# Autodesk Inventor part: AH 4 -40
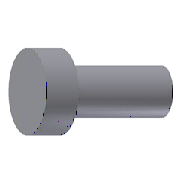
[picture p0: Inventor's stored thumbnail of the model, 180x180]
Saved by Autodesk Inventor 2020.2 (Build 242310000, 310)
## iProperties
Manager: www.cadconsulting.pl
Company: Fabian Stasiak CAD Consulting
Created: 2014-02
Part Number: AH 4 -40
Material: DIN 1.2210
Description: Ejector pins-hardened
Document SubType Name: Modeling
Standard: DIN 1530/ISO 6751
Designer: F.Stasiak
Standard Revision: 1
Manufacturer: DME
Language: pl-PL
Size Designation: 4 -40
Categories: <MemberInstance><Categories><Category DisplayName="Forma wtryskowa" InternalName="349578f2-f4d4-4954-8c09-8e99297a61c0" Mnemonic="MOLD"><Category DisplayName="K
Mass: 0.191827 g
Surface Area: 2.51725 cm^2
Volume: 0.191827 cm^3
Density: 7.85 g/cm^3
Appearance: Aluminium - ciemne
Catalog Web Link: www.expertbooks.pl
IsCustomPart: 1
Author: F.Stasiak
Subject: Zbiór ćwiczeń. Autodesk Inventor 2020. Kurs Professional
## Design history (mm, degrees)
sketch "Sketch1"
  geometry: L1 (0, 4)-(3, 4); L2 (0, 0)-(0, 4); L3 (3, 2)-(40, 2); L4 (40, 2)-(40, 0); L5 (0, 0)-(40, 0); L6 (3, 4)-(3, 2); 2 further points
  constraints: 12 end point, 4 point on line, 2 horizontal, 2 perpendicular, 1 coincident
  dimensions: "d6" = 3 distance of L1.start L1.end (derived); "d9" = 40 distance between parallel lines of L4 L2 (derived); "d10" = 8 diameter of L1 L5 (derived); "d13" = 4 diameter of L3 L5 (derived)
revolve "Revolution1" sketch "Sketch1" stored, may be unused: angle "d11" = 90 deg
fillet "Fillet1" dims "d29" = 0.3 (derived)
workplane "Work Plane1"
sketch "Sketch2"
  geometry: L1 (4, -1.5)-(-4, -1.5) reference; L2 (-4, -1.5)-(-4, 1.5) reference; 4 further points
  constraints: 2 midpoint, 1 horizontal alignment, 1 vertical alignment
hole "Anti_Rotary Hole" sketch "Sketch2" at (0, 0) diameter "d44" = 0.55 (derived); stored, may be unused: countersink angle "d48" = 90 deg, drill point angle "d50" = 118 deg; dims "d45" = 6, "d46" = 4, "d47" = 2, "d49" = 0.825 (derived)
sketch "Sketch3"
  geometry: L1 (-2.3, 3.273)-(-2.3, -3.273); A1 r 4 centre (0, 0) between (-2.3, 3.273) and (-2.3, -3.273) reference; 1 further point
  constraints: 2 end point, 2 point on circle, 1 vertical
  dimensions: "d55" = 2.3 distance from line of point (0, 0) L1 (derived)
extrude "Anti_Rotary Plane" cut sketch "Sketch3" distance "d42" = 3.3 (derived); taper "d43" = 0 deg
body "Solid1"
node "Projected Loop1"
other parameters: "d15" = 0, "d24" = 0, "P" = 4 [user parameter], "T_" = 3 [user parameter], "H_" = 8 [user parameter], "R" = 0.3 [user parameter], "Anti_Rotary_P" = 2.3 [user parameter], "Anti_Rotary_D" = 0.55 [user parameter], "d51" = 0, "d54" = 0, "d56" = 0, "d57" = 0
